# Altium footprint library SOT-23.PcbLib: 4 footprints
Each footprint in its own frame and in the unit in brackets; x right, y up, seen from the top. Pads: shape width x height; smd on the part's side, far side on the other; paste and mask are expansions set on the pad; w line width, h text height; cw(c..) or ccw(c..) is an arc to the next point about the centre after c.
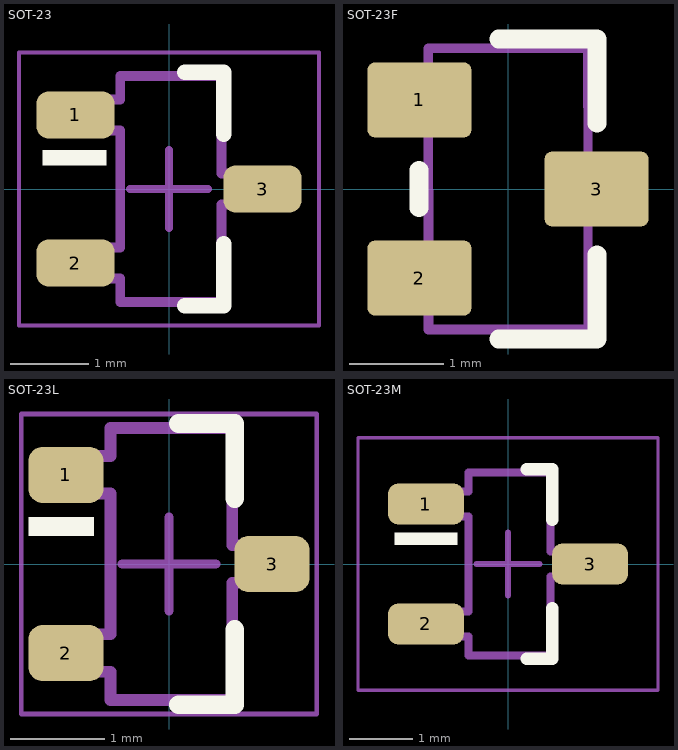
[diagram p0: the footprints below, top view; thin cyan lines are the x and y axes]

## SOT-23 [mm] "SOT23, 3-Leads, Body 2.9x1.3mm, Pitch 0.95mm, Lead Span 2.5mm, IPC Medium Density"
height 1.1
pads (3):
  rrect50% 1x0.6 smd: 1(-1.2,0.95) 2(-1.2,-0.95) 3(1.2,0)
Top Overlay:
  rectangle: -1.625,0.3 -0.8,0.5
  lines w0.2: 0.2,-1.5 0.7,-1.5 0.7,-0.7 ; 0.2,1.5 0.7,1.5 0.7,0.7
M5 Assembly Top:
  lines w0.127: -1.16,-1.15 -1.16,-0.75 -0.625,-0.75 -0.625,0.75 -1.16,0.75 -1.16,1.15 -0.625,1.15 -0.625,1.45 0.675,1.45 0.675,0.2 1.21,0.2 1.21,-0.2 0.675,-0.2 0.675,-1.45 -0.625,-1.45 -0.625,-1.15 -1.16,-1.15
  text ".Designator" at -0.175,1.225 h0.64
M15  Courtyards Top:
  lines w0.05: -1.925,-1.75 1.925,-1.75 1.925,1.75 -1.925,1.75 -1.925,-1.75
  lines w0.1: -0.5,0 0.5,0 ; 0,-0.5 0,0.5
3D body: height 1, standoff 0, extent -1.16,-1.45 1.21,1.45

## SOT-23F [mm] "Zetex recommended land pattern Rev 81 ap02001.pdf"
height 1
pads (3):
  rrect20% 1.11x0.8 smd: 1(-0.945,0.95) 2(-0.945,-0.95) 3(0.945,0)
Top Overlay:
  lines w0.2: -0.95,-0.2 -0.95,0.2 ; -0.1,-1.6 0.95,-1.6 0.95,-0.7 ; -0.1,1.6 0.95,1.6 0.95,0.7
M5 Assembly Top:
  lines w0.1: -0.85,1.5 -0.844,-1.496 0.85,-1.496 ; -0.85,1.5 -0.85,1.175 -1.25,1.175 -1.25,0.725 -0.85,0.725 -0.85,-0.725 -1.25,-0.725 -1.25,-1.175 -0.85,-1.175 -0.85,-1.5 0.85,-1.5 0.85,-1.496 ; -0.85,1.5 0.85,1.5 0.853,0.225 ; 0.85,-1.496 0.856,-1.496 0.854,-0.225 ; 0.853,0.225 1.25,0.225 1.25,-0.225 0.854,-0.225 ; 0.853,0.225 0.854,-0.225
  text ".Designator" at -0.3,0.9 h0.51
3D body: height 1, standoff 0, extent -1.25,-1.5 1.25,1.5

## SOT-23L [mm] "SOT23, 3-Leads, Body 2.9x1.3mm, Pitch 0.95mm, Lead Span 2.5mm, IPC High Density"
height 1.1
pads (3):
  rrect50% 0.8x0.6 smd: 1(-1.1,0.95) 2(-1.1,-0.95) 3(1.1,0)
Top Overlay:
  rectangle: -1.5,0.3 -0.8,0.5
  lines w0.2: 0.1,-1.5 0.7,-1.5 0.7,-0.7 ; 0.1,1.5 0.7,1.5 0.7,0.7
M5 Assembly Top:
  lines w0.127: -1.16,-1.15 -1.16,-0.75 -0.625,-0.75 -0.625,0.75 -1.16,0.75 -1.16,1.15 -0.625,1.15 -0.625,1.45 0.675,1.45 0.675,0.2 1.21,0.2 1.21,-0.2 0.675,-0.2 0.675,-1.45 -0.625,-1.45 -0.625,-1.15 -1.16,-1.15
  text ".Designator" at -0.175,1.225 h0.64
M15  Courtyards Top:
  lines w0.05: -1.575,-1.6 1.575,-1.6 1.575,1.6 -1.575,1.6 -1.575,-1.6
  lines w0.1: -0.5,0 0.5,0 ; 0,-0.5 0,0.5
3D body: height 1, standoff 0, extent -1.16,-1.45 1.21,1.45

## SOT-23M [mm] "SOT23, 3-Leads, Body 2.9x1.3mm, Pitch 0.95mm, Lead Span 2.5mm, IPC Low Density"
height 1.1
pads (3):
  rrect50% 1.2x0.65 smd: 1(-1.3,0.95) 2(-1.3,-0.95) 3(1.3,0)
Top Overlay:
  rectangle: -1.8,0.3 -0.8,0.5
  lines w0.2: 0.3,-1.5 0.7,-1.5 0.7,-0.7 ; 0.3,1.5 0.7,1.5 0.7,0.7
M5 Assembly Top:
  lines w0.127: -1.16,-1.15 -1.16,-0.75 -0.625,-0.75 -0.625,0.75 -1.16,0.75 -1.16,1.15 -0.625,1.15 -0.625,1.45 0.675,1.45 0.675,0.2 1.21,0.2 1.21,-0.2 0.675,-0.2 0.675,-1.45 -0.625,-1.45 -0.625,-1.15 -1.16,-1.15
  text ".Designator" at -0.175,1.225 h0.64
M15  Courtyards Top:
  lines w0.05: -2.375,-2 -2.375,2 2.375,2 2.375,-2 -2.375,-2
  lines w0.1: -0.5,0 0.5,0 ; 0,-0.5 0,0.5
3D body: height 1, standoff 0, extent -1.16,-1.45 1.21,1.45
